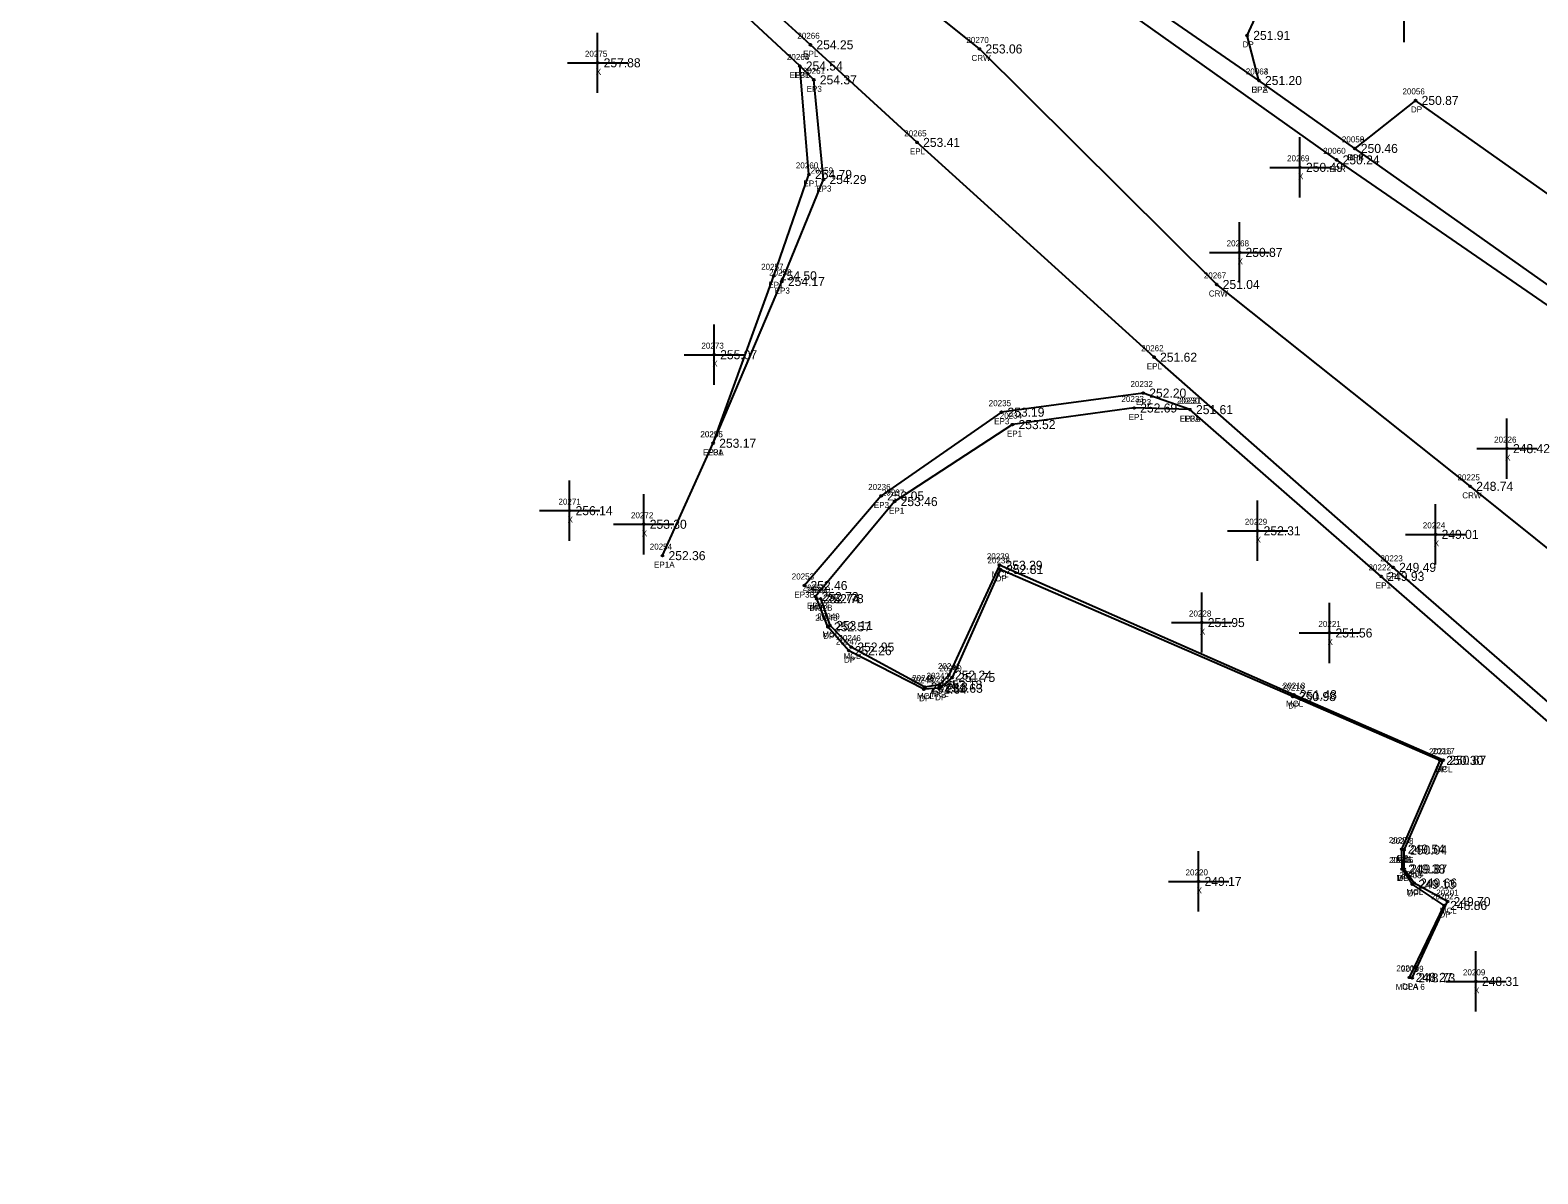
# Model space of a CAD drawing. Extents: x 1961330 to 1962287, y 800294 to 801079.
# Drawn here: x 1961887.6 to 1962137.8, y 800315.7 to 800505.6 of the extents above; entities that cross this region are included whole.
import ezdxf

# ---------------------------------------------------------------- set-up
doc = ezdxf.new("R2010")
doc.units = 0
for name, color, linetype in [('RD_DTM_BkLn1', 7, 'Continuous'), ('RD_EX_Conc', 7, 'Continuous'), ('RD_EX_Conc_txCode', 7, 'Continuous'), ('RD_EX_Driveway', 7, 'Continuous'), ('RD_EX_Driveway_txCode', 7, 'Continuous'), ('RD_EX_Misc', 7, 'Continuous'), ('RD_EX_Misc_txCode', 7, 'Continuous'), ('RD_EX_Road', 7, 'Continuous'), ('RD_EX_Road_txCode', 7, 'Continuous'), ('RD_EX_TX_Conc_ELEV', 7, 'Continuous'), ('RD_EX_TX_Driveway_ELEV', 7, 'Continuous'), ('RD_EX_TX_Misc_ELEV', 7, 'Continuous'), ('RD_EX_TX_Road_ELEV', 7, 'Continuous'), ('RD_HC_Survey_ELEV', 7, 'Continuous'), ('RD_HC_Survey_txCode', 7, 'Continuous'), ('RD_SMD_Locator', 7, 'Continuous')]:
    doc.layers.add(name, color=color, linetype=linetype)

msp = doc.modelspace()

# ---------------------------------------------------------------- linework, layer by layer
at = {"layer": 'RD_DTM_BkLn1'}
msp.add_lwpolyline([(1962257.08, 800334.72), (1962203.79, 800372.43), (1962164.31, 800399.58), (1962126.58, 800429.85), (1962084.5, 800463.37), (1962045.12, 800502.48), (1962010.49, 800530.36), (1961971.27, 800562.01), (1961931.18, 800594.14), (1961890.91, 800625.98), (1961844.41, 800662.62), (1961808.07, 800691.13), (1961729.11, 800753.37), (1961696.19, 800780.32), (1961667.25, 800802.66), (1961624.93, 800836.78), (1961588.01, 800866), (1961545.37, 800899.49), (1961472.25, 800957.29), (1961437.91, 800983.99), (1961399.03, 801013.16), (1961365.01, 801035.89)], dxfattribs=at)
at = {"layer": 'RD_EX_Conc'}
msp.add_lwpolyline([(1962116.95, 800348.23), (1962122.81, 800360.89), (1962117.26, 800363.98), (1962115.61, 800366.3), (1962115.6, 800369.46), (1962122.1, 800384.38), (1962097.31, 800395.25), (1962048.46, 800416.74), (1962040.07, 800398.5), (1962038.47, 800396.89), (1962036.05, 800396.52), (1962023.86, 800403.16), (1962020.33, 800406.75), (1962018.78, 800411.2)], dxfattribs=at)
at = {"layer": 'RD_EX_Driveway'}
for points in [[(1962091.52, 800497.24), (1962089.57, 800504.73), (1962092.49, 800511.12), (1962102.73, 800516.99), (1962107.6, 800525.32), (1962111.65, 800535.64)], [(1962171.38, 800493.75), (1962163.68, 800485.64), (1962177.97, 800474.42), (1962166.53, 800458.03), (1962152.89, 800453.77), (1962153.39, 800455.94), (1962150.83, 800460.97), (1962153.43, 800468.5), (1962117.51, 800493.93), (1962107.43, 800485.96)], [(1962116.51, 800348.31), (1962122.25, 800360.25), (1962116.96, 800363.77), (1962115.29, 800366.3), (1962115.23, 800369.61), (1962121.6, 800384.34), (1962097.15, 800394.94), (1962048.58, 800416.05), (1962040.61, 800398.11), (1962038.55, 800396.32), (1962035.9, 800396.16), (1962023.43, 800402.56), (1962019.98, 800406.52), (1962018.15, 800411.16)]]:
    msp.add_lwpolyline(points, dxfattribs=at)
at = {"layer": 'RD_EX_Misc'}
for p, q in [((1962115.59, 800503.6), (1962115.59, 800513.6)), ((1961981.76, 800495.18), (1961981.76, 800505.18)), ((1961976.76, 800500.18), (1961986.76, 800500.18)), ((1962098.32, 800477.82), (1962098.32, 800487.82)), ((1962093.32, 800482.82), (1962103.32, 800482.82)), ((1962088.29, 800463.7), (1962088.29, 800473.7)), ((1962083.29, 800468.7), (1962093.29, 800468.7)), ((1962001.1, 800446.71), (1962001.1, 800456.71)), ((1961996.1, 800451.71), (1962006.1, 800451.71)), ((1962132.68, 800431.11), (1962132.68, 800441.11)), ((1962127.68, 800436.11), (1962137.68, 800436.11)), ((1961977.1, 800420.81), (1961977.1, 800430.81)), ((1961989.41, 800418.55), (1961989.41, 800428.55)), ((1962091.29, 800417.47), (1962091.29, 800427.47)), ((1962120.83, 800416.87), (1962120.83, 800426.87)), ((1961972.1, 800425.81), (1961982.1, 800425.81)), ((1961984.41, 800423.55), (1961994.41, 800423.55)), ((1962086.29, 800422.47), (1962096.29, 800422.47)), ((1962115.83, 800421.87), (1962125.83, 800421.87)), ((1962082.02, 800402.23), (1962082.02, 800412.23)), ((1962103.21, 800400.5), (1962103.21, 800410.5)), ((1962077.02, 800407.23), (1962087.02, 800407.23)), ((1962098.21, 800405.5), (1962108.21, 800405.5)), ((1962081.49, 800359.24), (1962081.49, 800369.24)), ((1962076.49, 800364.24), (1962086.49, 800364.24)), ((1962127.52, 800342.64), (1962127.52, 800352.64)), ((1962122.52, 800347.64), (1962132.52, 800347.64))]:
    msp.add_line(p, q, dxfattribs=at)
at = {"layer": 'RD_EX_Road'}
for points in [[(1962276.74, 800366.53), (1962275.76, 800367.28), (1962226.46, 800400.66), (1962183.05, 800429.73), (1962145.98, 800455.38), (1962104.4, 800484.06), (1962056.77, 800517.94), (1962023.95, 800541.05), (1961991.87, 800563.56), (1961983.89, 800569.94), (1961938.77, 800603.67), (1961913.43, 800623.83), (1961897.73, 800636.17), (1961851.62, 800671.61), (1961815.86, 800699.48), (1961795.77, 800715.49), (1961771.88, 800733.73), (1961750.77, 800750.96), (1961735.63, 800762.82), (1961702.92, 800788.52), (1961676.16, 800810.27), (1961651.45, 800830.73), (1961641.14, 800839.02)], [(1962241.79, 800315.68), (1962238.35, 800317.6), (1962189.92, 800352.69), (1962151.64, 800383.49), (1962113.78, 800416.39), (1962074.11, 800451.29), (1962034.78, 800486.96), (1962017.07, 800503.17), (1961999.46, 800519.25), (1961962.48, 800552.12), (1961937.08, 800573.11), (1961923.19, 800584.9), (1961883.07, 800617.43), (1961838.29, 800653.43), (1961801.42, 800682.57), (1961728.41, 800740.86), (1961722.95, 800745.11), (1961689.13, 800771.93), (1961670.14, 800787.03), (1961660.52, 800795.31), (1961637.49, 800813.67)], [(1961992.53, 800418.34), (1962000.94, 800437), (1962011.01, 800464.81), (1962016.84, 800481.64), (1962015.31, 800499.65), (1961996.99, 800516.71), (1961979.47, 800530.76), (1961969.8, 800538.75), (1961958.28, 800547.16), (1961941.07, 800560.82), (1961925.41, 800573.41), (1961918.19, 800579.25), (1961879.32, 800611.18), (1961866.07, 800621.08), (1961838.29, 800653.43)], [(1962275.76, 800367.28), (1962274.03, 800371.18), (1962275.17, 800373.82), (1962239.93, 800394.94), (1962227.76, 800403.12), (1962207.73, 800416.44), (1962184.45, 800431.68), (1962152.89, 800453.77), (1962107.43, 800485.96), (1962091.52, 800497.24), (1962058.28, 800520.2), (1962027.14, 800543.26), (1961995.14, 800564.69), (1961983.89, 800569.94)], [(1962000.94, 800437), (1962012.34, 800463.86), (1962019.24, 800480.8), (1962017.64, 800497.35), (1962015.31, 800499.65)], [(1962080.07, 800442.59), (1962072.31, 800445.34), (1962048.78, 800442.16), (1962028.81, 800428.25), (1962016.09, 800413.38)], [(1962238.35, 800317.6), (1962235.93, 800316.57), (1962188.31, 800350.58), (1962150.21, 800381.44), (1962111.82, 800414.89), (1962080.07, 800442.59), (1962070.81, 800442.86), (1962050.61, 800440.1), (1962031.05, 800427.32), (1962017.92, 800411.54)]]:
    msp.add_lwpolyline(points, dxfattribs=at)
at = {"layer": 'RD_SMD_Locator'}
for centre in [(1962089.57, 800504.73), (1962017.07, 800503.17), (1962045.12, 800502.48), (1961981.76, 800500.18), (1962015.31, 800499.65), (1962015.31, 800499.65), (1962017.64, 800497.35), (1962091.52, 800497.24), (1962091.52, 800497.24), (1962117.51, 800493.93), (1962034.78, 800486.96), (1962104.4, 800484.06), (1962107.43, 800485.96), (1962107.43, 800485.96), (1962016.84, 800481.64), (1962098.32, 800482.82), (1962019.24, 800480.8), (1962088.29, 800468.7), (1962011.01, 800464.81), (1962012.34, 800463.86), (1962084.5, 800463.37), (1962001.1, 800451.71), (1962074.11, 800451.29), (1962072.31, 800445.34), (1962048.78, 800442.16), (1962070.81, 800442.86), (1962080.07, 800442.59), (1962080.07, 800442.59), (1962050.61, 800440.1), (1962000.94, 800437), (1962000.94, 800437), (1962132.68, 800436.11), (1962126.58, 800429.85), (1962028.81, 800428.25), (1962031.05, 800427.32), (1961977.1, 800425.81), (1961989.41, 800423.55), (1962091.29, 800422.47), (1962120.83, 800421.87), (1961992.53, 800418.34), (1962048.46, 800416.74), (1962113.78, 800416.39), (1962048.58, 800416.05), (1962111.82, 800414.89), (1962016.09, 800413.38), (1962017.92, 800411.54), (1962018.78, 800411.2), (1962018.15, 800411.16), (1962019.98, 800406.52), (1962020.33, 800406.75), (1962082.02, 800407.23), (1962103.21, 800405.5), (1962023.43, 800402.56), (1962023.86, 800403.16), (1962036.05, 800396.52), (1962038.47, 800396.89), (1962038.55, 800396.32), (1962040.07, 800398.5), (1962040.61, 800398.11), (1962035.9, 800396.16), (1962097.15, 800394.94), (1962097.31, 800395.25), (1962121.6, 800384.34), (1962122.1, 800384.38), (1962115.23, 800369.61), (1962115.6, 800369.46), (1962115.29, 800366.3), (1962115.61, 800366.3), (1962081.49, 800364.24), (1962116.96, 800363.77), (1962117.26, 800363.98), (1962122.25, 800360.25), (1962122.81, 800360.89), (1962116.51, 800348.31), (1962116.95, 800348.23), (1962127.52, 800347.64)]:
    msp.add_circle(centre, 0.15, dxfattribs=at)

# ---------------------------------------------------------------- texts
at = {"layer": 'RD_EX_Conc_txCode'}
for s, p in [('20239', (1962046.35, 800417.74)), ('MCL', (1962047.17, 800414.74)), ('20250', (1962016.62, 800412.2)), ('MCLB', (1962017.02, 800409.2)), ('20249', (1962018.22, 800407.75)), ('MCL', (1962019.04, 800404.75)), ('20246', (1962021.72, 800404.16)), ('MCL', (1962022.57, 800401.16)), ('20242', (1962036.35, 800397.89)), ('20241', (1962038.24, 800399.5)), ('20245', (1962033.94, 800397.52)), ('MCL', (1962038.78, 800396.5)), ('20218', (1962095.48, 800396.25)), ('MCL', (1962034.76, 800394.52)), ('MCL', (1962037.18, 800394.89)), ('MCL', (1962096.02, 800393.25)), ('20217', (1962120.27, 800385.38)), ('MCL', (1962120.81, 800382.38)), ('20208', (1962113.45, 800370.46)), ('20205', (1962113.45, 800367.3)), ('MCL', (1962114.31, 800367.46)), ('MCL', (1962114.32, 800364.3)), ('20204', (1962115.1, 800364.98)), ('MCL', (1962115.97, 800361.98)), ('20201', (1962120.94, 800361.89)), ('MCL', (1962121.52, 800358.89)), ('20199', (1962115.12, 800349.23)), ('MCLA 6', (1962114.21, 800346.23))]:
    msp.add_text(s, height=1, dxfattribs=at).set_placement(p)
at = {"layer": 'RD_EX_Driveway_txCode'}
for s, p in [('DP', (1962088.79, 800502.73)), ('20064', (1962089.34, 800498.24)), ('DPA', (1962090.25, 800495.24)), ('20056', (1962115.33, 800494.93)), ('DP', (1962116.73, 800491.93)), ('20058', (1962105.28, 800486.96)), ('DPB', (1962106.18, 800483.96)), ('20238', (1962046.46, 800417.05)), ('DP', (1962047.8, 800414.05)), ('20251', (1962016.31, 800412.16)), ('DPB', (1962016.89, 800409.16)), ('20248', (1962017.86, 800407.52)), ('DP', (1962019.2, 800404.52)), ('20247', (1962021.31, 800403.56)), ('DP', (1962022.65, 800400.56)), ('20240', (1962038.45, 800399.11)), ('20244', (1962033.78, 800397.16)), ('20243', (1962036.43, 800397.32)), ('DP', (1962039.83, 800396.11)), ('20219', (1962095.31, 800395.94)), ('DP', (1962035.12, 800394.16)), ('DP', (1962037.77, 800394.32)), ('DP', (1962096.37, 800392.94)), ('20216', (1962119.74, 800385.34)), ('DP', (1962120.82, 800382.34)), ('20207', (1962113.07, 800370.61)), ('20206', (1962113.1, 800367.3)), ('DP', (1962114.45, 800367.61)), ('DP', (1962114.51, 800364.3)), ('20203', (1962114.8, 800364.77)), ('DP', (1962116.18, 800361.77)), ('20202', (1962120.09, 800361.25)), ('DP', (1962121.47, 800358.25)), ('20200', (1962114.31, 800349.31)), ('DPA', (1962115.24, 800346.31))]:
    msp.add_text(s, height=1, dxfattribs=at).set_placement(p)
at = {"layer": 'RD_EX_Misc_txCode'}
for s, p in [('20275', (1961979.65, 800501.18)), ('X', (1961981.45, 800498.18)), ('20269', (1962096.18, 800483.82)), ('X', (1962098, 800480.82)), ('20268', (1962086.15, 800469.7)), ('X', (1962087.97, 800466.7)), ('20273', (1961998.98, 800452.71)), ('X', (1962000.79, 800449.71)), ('20226', (1962130.54, 800437.11)), ('X', (1962132.37, 800434.11)), ('20271', (1961975.26, 800426.81)), ('X', (1961976.78, 800423.81)), ('20272', (1961987.29, 800424.55)), ('20229', (1962089.17, 800423.47)), ('20224', (1962118.71, 800422.87)), ('X', (1961989.09, 800421.55)), ('X', (1962090.97, 800420.47)), ('X', (1962120.52, 800419.87)), ('20228', (1962079.9, 800408.23)), ('20221', (1962101.38, 800406.5)), ('X', (1962081.7, 800405.23)), ('X', (1962102.9, 800403.5)), ('20220', (1962079.33, 800365.24)), ('X', (1962081.17, 800362.24)), ('20209', (1962125.37, 800348.64)), ('X', (1962127.21, 800345.64))]:
    msp.add_text(s, height=1, dxfattribs=at).set_placement(p)
at = {"layer": 'RD_EX_Road_txCode'}
for s, p in [('20266', (1962014.9, 800504.17)), ('20263', (1962013.17, 800500.65)), ('20264', (1962013.17, 800500.65)), ('EPL', (1962015.87, 800501.17)), ('20261', (1962015.79, 800498.35)), ('20063', (1962089.34, 800498.24)), ('EP3B', (1962013.64, 800497.65)), ('EP1', (1962014.39, 800497.65)), ('EP3', (1962016.44, 800495.35)), ('EP2', (1962090.32, 800495.24)), ('20265', (1962032.64, 800487.96)), ('20059', (1962105.28, 800486.96)), ('EPL', (1962033.58, 800484.96)), ('20060', (1962102.18, 800485.06)), ('EP2', (1962106.23, 800483.96)), ('20260', (1962014.66, 800482.64)), ('20259', (1962017.12, 800481.8)), ('EPR', (1962103.17, 800482.06)), ('EP1', (1962015.92, 800479.64)), ('EP3', (1962018.04, 800478.8)), ('20257', (1962008.89, 800465.81)), ('20258', (1962010.22, 800464.86)), ('EP1', (1962010.09, 800462.81)), ('EP3', (1962011.14, 800461.86)), ('20262', (1962071.97, 800452.29)), ('EPL', (1962072.9, 800449.29)), ('20232', (1962070.19, 800446.34)), ('20235', (1962046.66, 800443.16)), ('20233', (1962068.69, 800443.86)), ('EP3', (1962071.1, 800443.34)), ('20230', (1962077.91, 800443.59)), ('20231', (1962078.24, 800443.59)), ('20234', (1962048.49, 800441.1)), ('EP1', (1962069.89, 800440.86)), ('EP3A', (1962078.38, 800440.59)), ('EP1', (1962079.15, 800440.59)), ('20256', (1961998.8, 800438)), ('20255', (1961998.83, 800438)), ('EP3', (1962047.57, 800440.16)), ('EP1', (1962049.69, 800438.1)), ('EP3A', (1961999.25, 800435)), ('EP1', (1962000.02, 800435)), ('20236', (1962026.66, 800429.25)), ('20237', (1962028.93, 800428.32)), ('EP3', (1962027.6, 800426.25)), ('EP1', (1962030.12, 800425.32)), ('20254', (1961990.41, 800419.34)), ('EP1A', (1961991.12, 800416.34)), ('20222', (1962109.7, 800415.89)), ('20223', (1962111.66, 800417.39)), ('20253', (1962013.97, 800414.38)), ('EP1', (1962110.9, 800412.89)), ('EPL', (1962112.58, 800414.39)), ('EP3B', (1962014.41, 800411.38)), ('20252', (1962015.8, 800412.54)), ('EP1B', (1962016.52, 800409.54))]:
    msp.add_text(s, height=1, dxfattribs=at).set_placement(p)
at = {"layer": 'RD_EX_TX_Conc_ELEV'}
for s, p in [('253.29', (1962049.46, 800415.99)), ('252.78', (1962019.78, 800410.45)), ('253.11', (1962021.33, 800406)), ('252.95', (1962024.86, 800402.41)), ('252.24', (1962041.07, 800397.75)), ('252.18', (1962037.05, 800395.77)), ('252.18', (1962039.47, 800396.14)), ('251.48', (1962098.31, 800394.5)), ('250.87', (1962123.1, 800383.63)), ('250.04', (1962116.6, 800368.71)), ('249.87', (1962116.61, 800365.55)), ('249.66', (1962118.26, 800363.23)), ('249.70', (1962123.81, 800360.14)), ('248.73', (1962117.95, 800347.48))]:
    msp.add_text(s, height=1.5, dxfattribs=at).set_placement(p)
at = {"layer": 'RD_EX_TX_Driveway_ELEV'}
for s, p in [('251.91', (1962090.57, 800503.98)), ('251.20', (1962092.52, 800496.49)), ('250.87', (1962118.51, 800493.18)), ('250.46', (1962108.43, 800485.21)), ('252.81', (1962049.58, 800415.3)), ('252.74', (1962019.15, 800410.41)), ('252.57', (1962020.98, 800405.77)), ('252.26', (1962024.43, 800401.81)), ('251.75', (1962041.61, 800397.36)), ('251.64', (1962036.9, 800395.41)), ('251.63', (1962039.55, 800395.57)), ('250.98', (1962098.15, 800394.19)), ('250.30', (1962122.6, 800383.59)), ('249.54', (1962116.23, 800368.86)), ('249.38', (1962116.29, 800365.55)), ('249.13', (1962117.96, 800363.02)), ('248.86', (1962123.25, 800359.5)), ('248.27', (1962117.51, 800347.56))]:
    msp.add_text(s, height=1.5, dxfattribs=at).set_placement(p)
at = {"layer": 'RD_EX_TX_Misc_ELEV'}
for s, p in [('257.88', (1961982.76, 800499.43)), ('250.49', (1962099.32, 800482.07)), ('250.87', (1962089.29, 800467.95)), ('255.07', (1962002.1, 800450.96)), ('248.42', (1962133.68, 800435.36)), ('256.14', (1961978.1, 800425.06)), ('253.30', (1961990.41, 800422.8)), ('252.31', (1962092.29, 800421.72)), ('249.01', (1962121.83, 800421.12)), ('251.95', (1962083.02, 800406.48)), ('251.56', (1962104.21, 800404.75)), ('249.17', (1962082.49, 800363.49)), ('248.31', (1962128.52, 800346.89))]:
    msp.add_text(s, height=1.5, dxfattribs=at).set_placement(p)
at = {"layer": 'RD_EX_TX_Road_ELEV'}
for s, p in [('254.25', (1962018.07, 800502.42)), ('254.54', (1962016.31, 800498.9)), ('254.54', (1962016.31, 800498.9)), ('254.37', (1962018.64, 800496.6)), ('251.20', (1962092.52, 800496.49)), ('253.41', (1962035.78, 800486.21)), ('250.46', (1962108.43, 800485.21)), ('250.24', (1962105.4, 800483.31)), ('254.79', (1962017.84, 800480.89)), ('254.29', (1962020.24, 800480.05)), ('254.50', (1962012.01, 800464.06)), ('254.17', (1962013.34, 800463.11)), ('251.62', (1962075.11, 800450.54)), ('252.20', (1962073.31, 800444.59)), ('253.19', (1962049.78, 800441.41)), ('252.69', (1962071.81, 800442.11)), ('251.61', (1962081.07, 800441.84)), ('251.61', (1962081.07, 800441.84)), ('253.52', (1962051.61, 800439.35)), ('253.17', (1962001.94, 800436.25)), ('253.17', (1962001.94, 800436.25)), ('253.05', (1962029.81, 800427.5)), ('253.46', (1962032.05, 800426.57)), ('252.36', (1961993.53, 800417.59)), ('249.49', (1962114.78, 800415.64)), ('252.46', (1962017.09, 800412.63)), ('249.93', (1962112.82, 800414.14)), ('252.73', (1962018.92, 800410.79))]:
    msp.add_text(s, height=1.5, dxfattribs=at).set_placement(p)
at = {"layer": 'RD_HC_Survey_ELEV'}
for s, p in [('253.06', (1962046.12, 800501.73)), ('251.04', (1962085.5, 800462.62)), ('248.74', (1962127.58, 800429.1))]:
    msp.add_text(s, height=1.5, dxfattribs=at).set_placement(p)
at = {"layer": 'RD_HC_Survey_txCode'}
for s, p in [('20270', (1962042.96, 800503.48)), ('CRW', (1962043.8, 800500.48)), ('20267', (1962082.36, 800464.37)), ('CRW', (1962083.19, 800461.37)), ('20225', (1962124.46, 800430.85)), ('CRW', (1962125.26, 800427.85))]:
    msp.add_text(s, height=1, dxfattribs=at).set_placement(p)

doc.saveas('drawing.dxf')
